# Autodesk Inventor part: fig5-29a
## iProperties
Created: 2005-12
Part Number: fig5-29a
Document SubType Name: Modeling
Designer: CADCIM
Density: 1 g/cm^3
Author: CADCIM
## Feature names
1. Extrusion1
